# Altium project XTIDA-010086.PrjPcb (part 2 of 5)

## Sheet XTIDA-010086_Power Stage.SchDoc: Power Stage
size 558 x 431 mm; Date: Not shown in title block; ApprovedBy: Not shown in title block; CheckedBy: Not shown in title block; Author: Not shown in title block; CompanyName: Not shown in title block; DrawnBy: Jeff Xie; Engineer: Not shown in title block; Organization: Not shown in title block; Address1: Not shown in title block; Address2: Not shown in title block; Address3: Not shown in title block; Address4: Not shown in title block; DocumentNumber: 2; Revision: Use project parameter SCH_Rev; SheetNumber: 4; SheetTotal: 8; PageSetup: Record=PageOptions¦CenterHorizontal=True¦CenterVertical=True¦PrintScale=1.00¦XCorrection=1.00¦YCorrection=1.00¦PrintKind=0¦BorderSize=5000000¦LeftOffset=0¦BottomOffset=0¦Orientation=2¦PaperLength=1000¦PaperWidth=1000¦Scale=100¦PaperSource=15¦PrintQuality=600¦MediaType=1¦DitherType=10¦PaperKind=Letter¦PrintScaleMode=1
Used 8 times, as channels MAIN SHEET/Ch1, MAIN SHEET/Ch2, MAIN SHEET/Ch3, MAIN SHEET/Ch4, MAIN SHEET/Ch5, MAIN SHEET/Ch6, MAIN SHEET/Ch7, MAIN SHEET/Ch8. Parts and nets are listed once, with the designators drawn on the sheet.
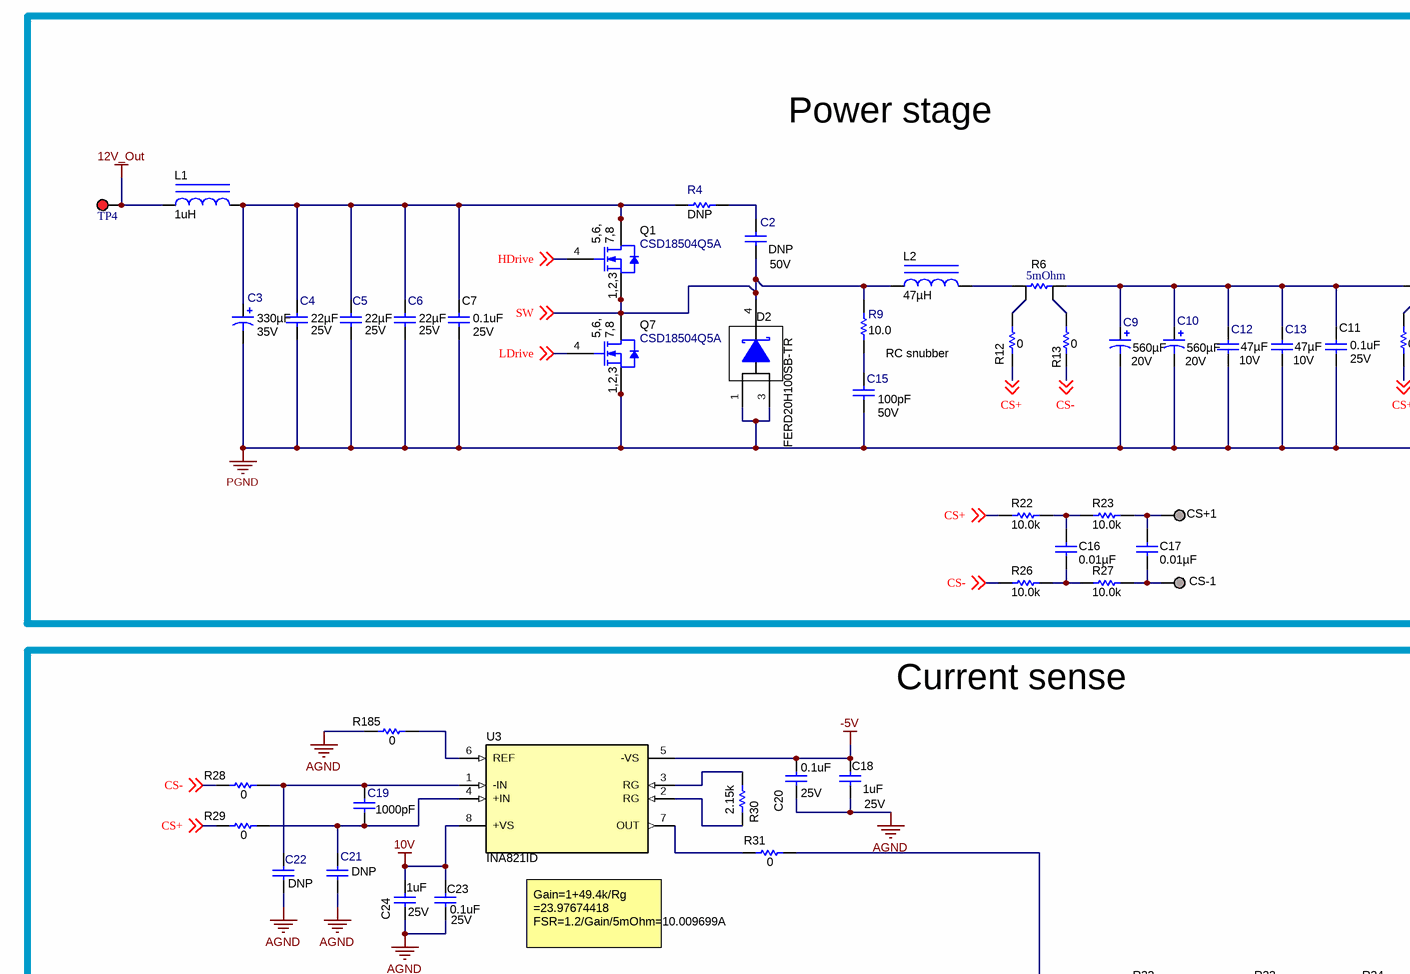
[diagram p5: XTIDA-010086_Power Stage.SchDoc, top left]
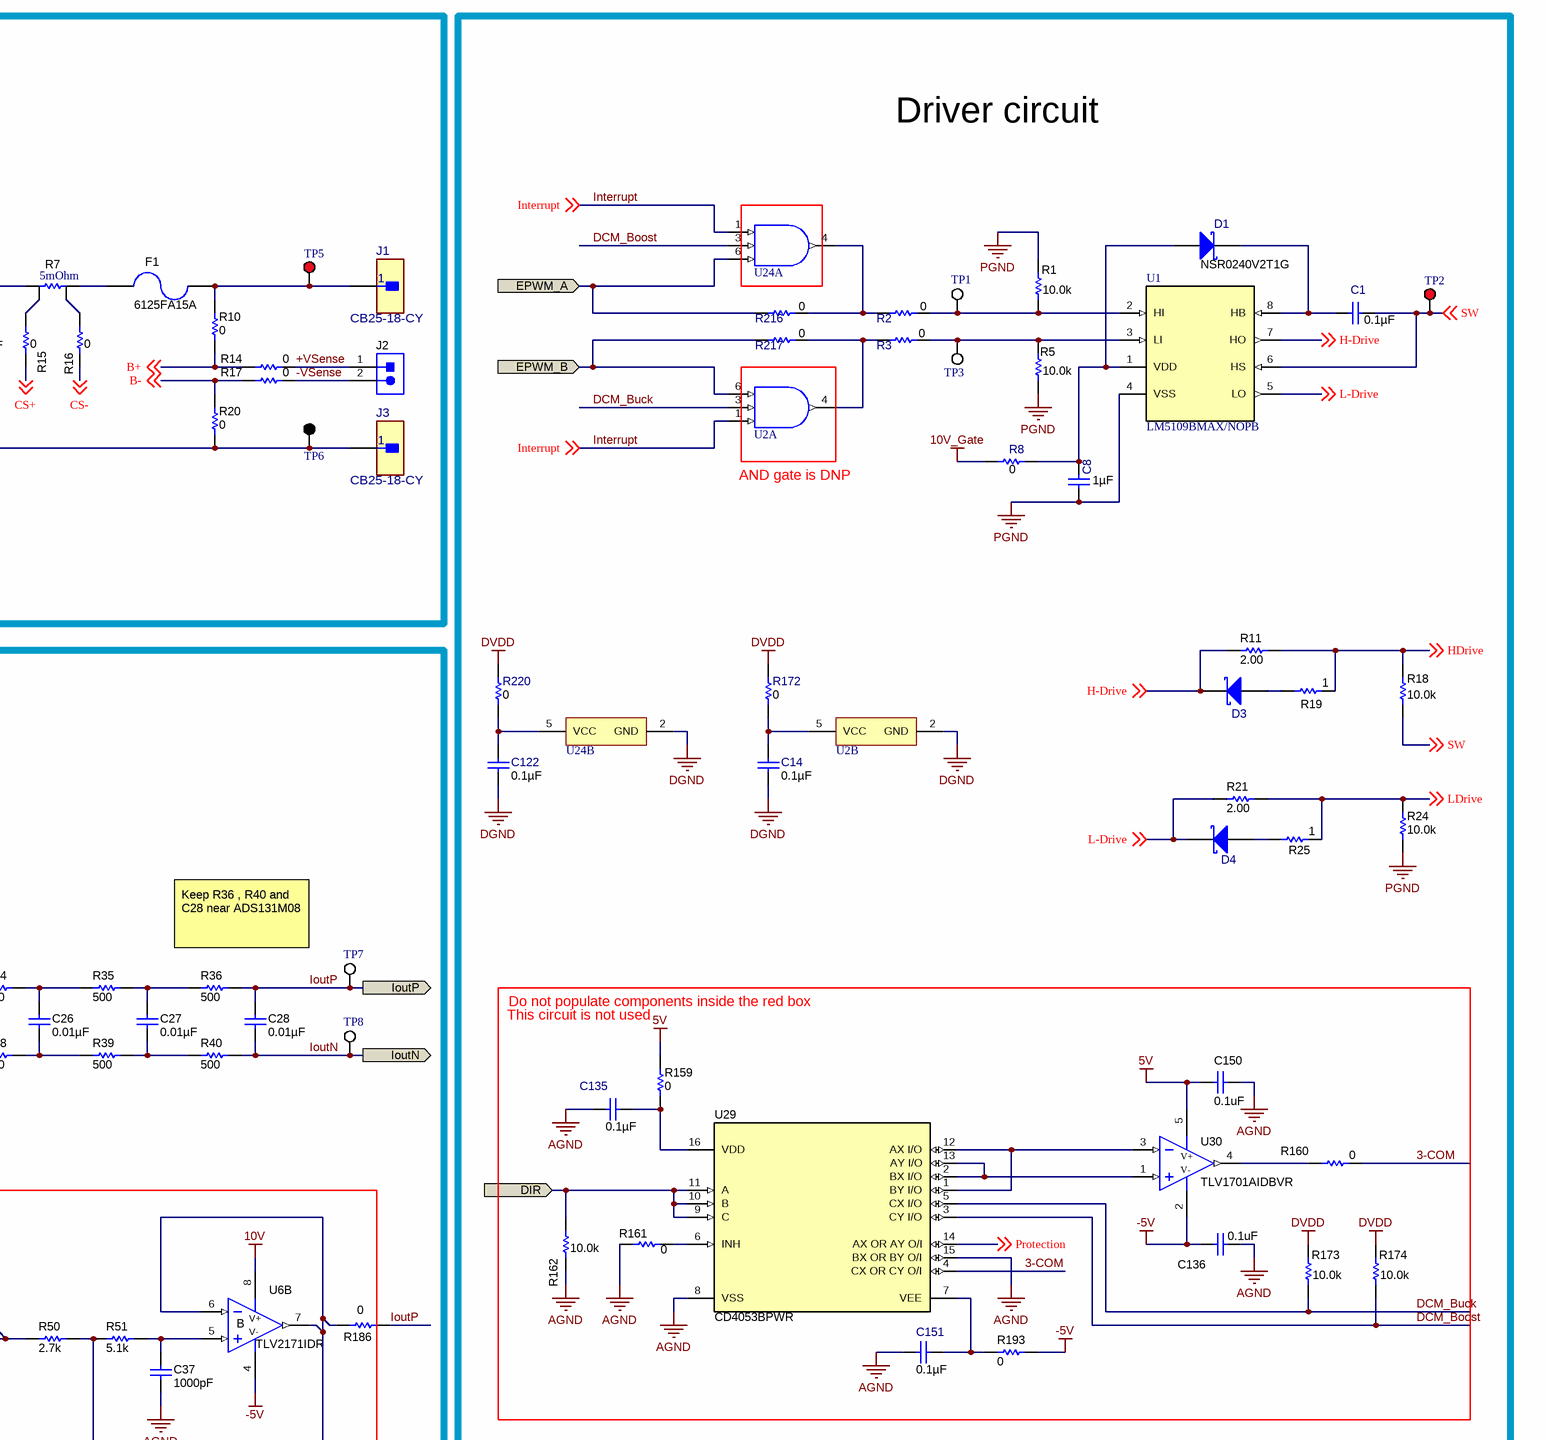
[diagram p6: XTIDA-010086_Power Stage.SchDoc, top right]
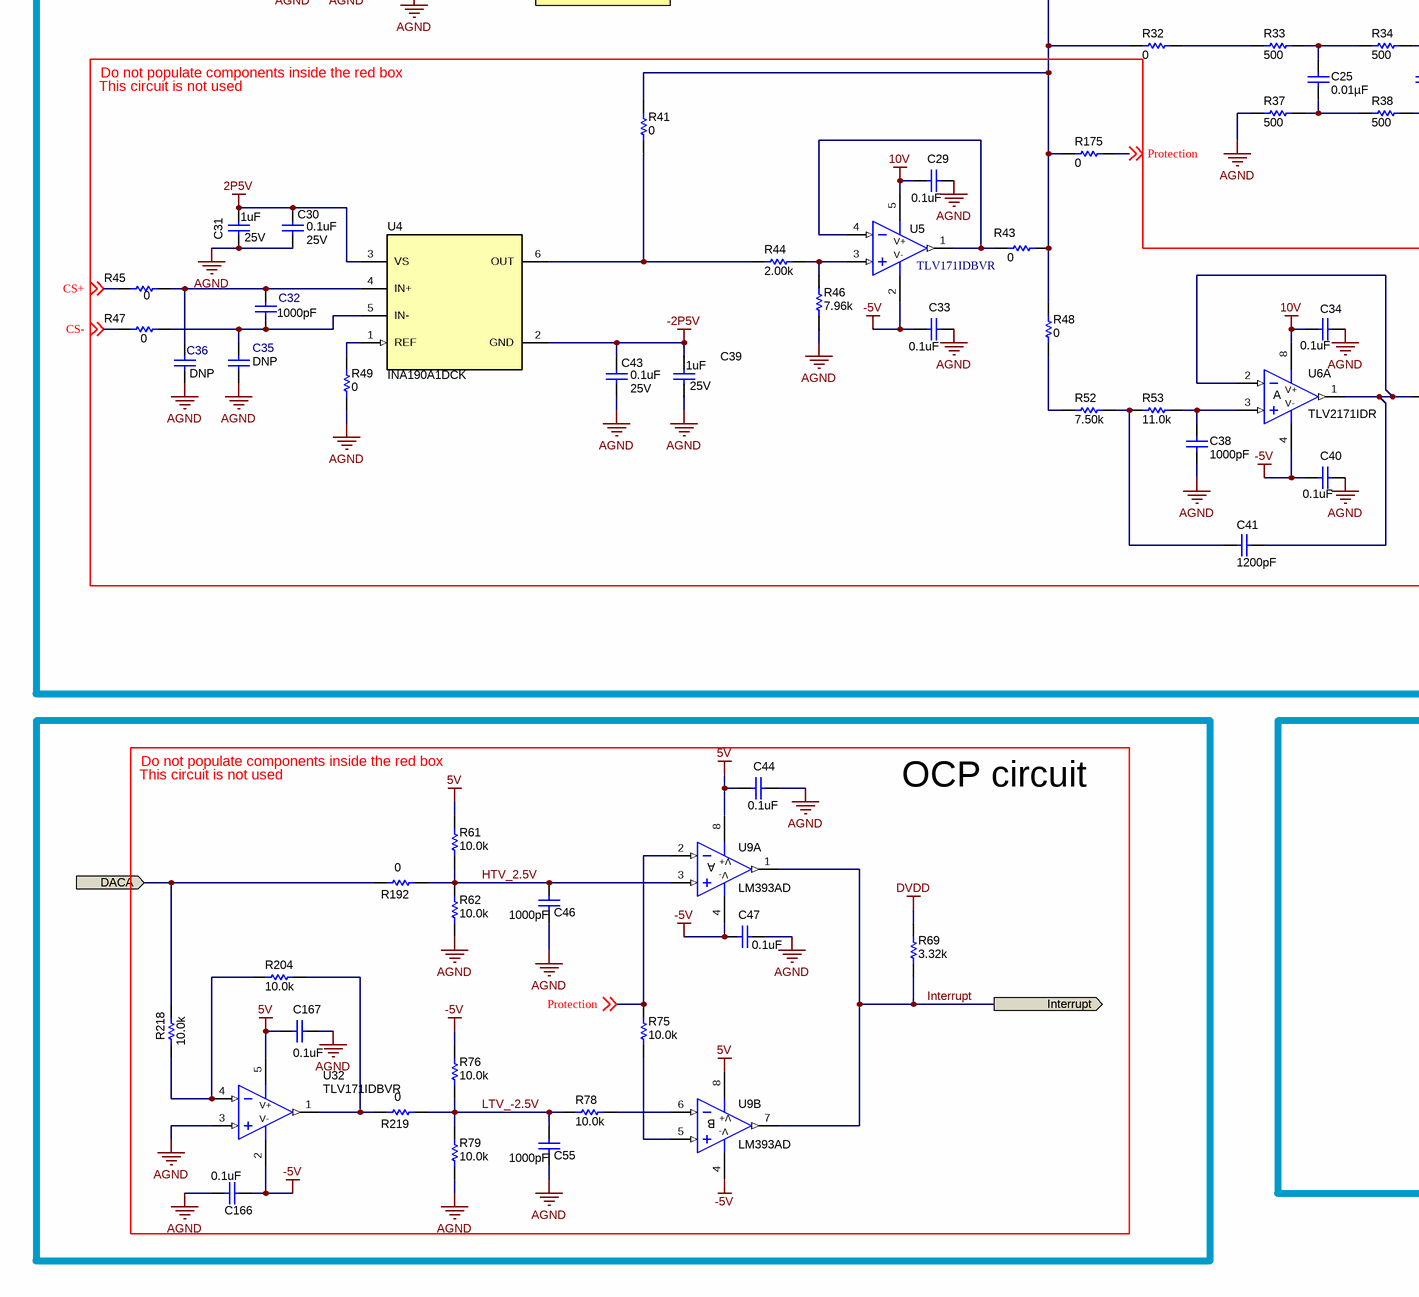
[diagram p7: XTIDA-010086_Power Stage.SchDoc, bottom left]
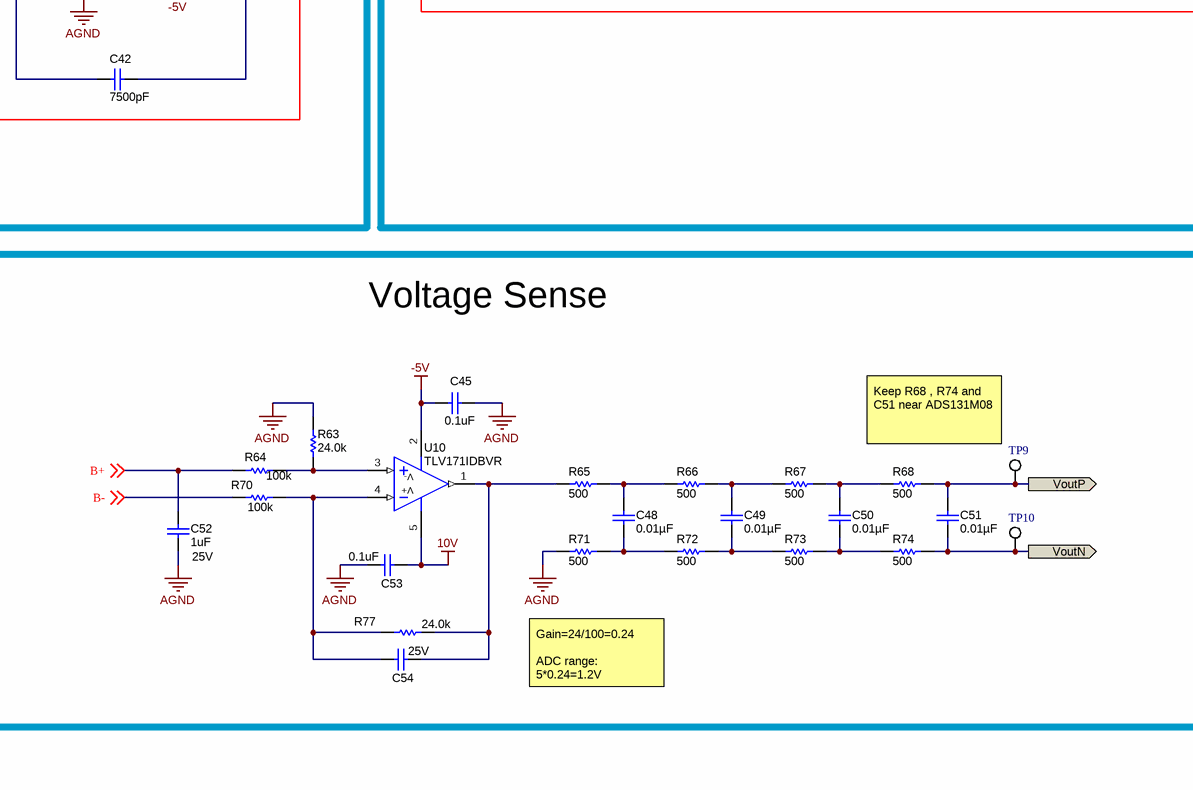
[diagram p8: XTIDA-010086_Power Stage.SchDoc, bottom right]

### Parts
C1  ValueDisplayed: 0.1µF  [0603L]  (hidden comment: C0603C104J3RACTU)
C2  ValueDisplayed: DNP  Value2: 50V  [0603L]  (hidden comment: GRM1885C1H101JA01D)
C3  ValueDisplayed: 330µF  Value2: 35V  [CAPSMT_62_F12]  (hidden comment: 35SVPK330M)
C4  ValueDisplayed: 22µF  Value2: 25V  [1210_270]  (hidden comment: GRM32ER71E226KE15L)
C5  ValueDisplayed: 22µF  Value2: 25V  [1210_270]  (hidden comment: GRM32ER71E226KE15L)
C6  ValueDisplayed: 22µF  Value2: 25V  [1210_270]  (hidden comment: GRM32ER71E226KE15L)
C7  ValueDisplayed: 0.1uF  Value2: 25V  [0603]  (hidden comment: Capacitor)
C8  ValueDisplayed: 1µF  [0603L]  (hidden comment: C0603C105K3RACTU)
C9  ValueDisplayed: 560µF  Value2: 20V  [SM_RADIAL_10AMM]  (hidden comment: 20SVF560M)
C10  ValueDisplayed: 560µF  Value2: 20V  [SM_RADIAL_10AMM]  (hidden comment: 20SVF560M)
C11  ValueDisplayed: 0.1uF  Value2: 25V  [0603]  (hidden comment: Capacitor)
C12  ValueDisplayed: 47µF  Value2: 10V  [1210_270]  (hidden comment: GRM32ER71A476ME15L)
C13  ValueDisplayed: 47µF  Value2: 10V  [1210_270]  (hidden comment: GRM32ER71A476ME15L)
C14  ValueDisplayed: 0.1µF  [0603L]  (hidden comment: C0603C104J3RACTU)
C15  ValueDisplayed: 100pF  Value2: 50V  [0603L]  (hidden comment: GRM1885C1H101JA01D)
C16  ValueDisplayed: 0.01µF  [0402]  (hidden comment: GCM155R71E103KA37D)
C17  ValueDisplayed: 0.01µF  [0402]  (hidden comment: GCM155R71E103KA37D)
C18  ValueDisplayed: 1uF  VDC_V: 25V  [0603]  (hidden comment: Capacitor)
C19  ValueDisplayed: 1000pF  [0603L]  (hidden comment: GRM1885C1H102JA01D)
C20  ValueDisplayed: 0.1uF  Value2: 25V  [0603]  (hidden comment: Capacitor)
C21  value DNP  [0603L]  (hidden comment: GRM1885C1H101JA01D)
C22  value DNP  [0603L]  (hidden comment: GRM1885C1H101JA01D)
C23  ValueDisplayed: 0.1uF  Value2: 25V  [0603]  (hidden comment: Capacitor)
C24  ValueDisplayed: 1uF  Value2: 25V  [0603]  (hidden comment: Capacitor)
C25  ValueDisplayed: 0.01µF  [0603]  (hidden comment: C0603C103J3GECAUTO)
C26  ValueDisplayed: 0.01µF  [0603]  (hidden comment: C0603C103J3GECAUTO)
C27  ValueDisplayed: 0.01µF  [0603]  (hidden comment: C0603C103J3GECAUTO)
C28  ValueDisplayed: 0.01µF  [0603]  (hidden comment: C0603C103J3GECAUTO)
C29  ValueDisplayed: 0.1uF  [0603]  (hidden comment: Capacitor)
C30  ValueDisplayed: 0.1uF  Value2: 25V  [0603]  (hidden comment: Capacitor)
C31  ValueDisplayed: 1uF  VDC_V: 25V  [0603]  (hidden comment: Capacitor)
C32  ValueDisplayed: 1000pF  [0603L]  (hidden comment: GRM1885C1H102JA01D)
C33  ValueDisplayed: 0.1uF  [0603]  (hidden comment: Capacitor)
C34  ValueDisplayed: 0.1uF  [0603]  (hidden comment: Capacitor)
C35  value DNP  [0603L]  (hidden comment: GRM1885C1H101JA01D)
C36  value DNP  [0603L]  (hidden comment: GRM1885C1H101JA01D)
C37  ValueDisplayed: 1000pF  [0402]  (hidden comment: 885012205044)
C38  ValueDisplayed: 1000pF  [0402]  (hidden comment: 885012205044)
C39  ValueDisplayed: 1uF  VDC_V: 25V  [0603]  (hidden comment: Capacitor)
C40  ValueDisplayed: 0.1uF  [0603]  (hidden comment: Capacitor)
C41  ValueDisplayed: 1200pF  [0402]  (hidden comment: GRM155R71H122KA01D)
C42  ValueDisplayed: 7500pF  [0805_HV]  (hidden comment: GRM2195C1H752JA01D)
C43  ValueDisplayed: 0.1uF  Value2: 25V  [0603]  (hidden comment: Capacitor)
C44  ValueDisplayed: 0.1uF  [0603]  (hidden comment: Capacitor)
C45  ValueDisplayed: 0.1uF  [0603]  (hidden comment: Capacitor)
C46  ValueDisplayed: 1000pF  [0603]  (hidden comment: 06031C102JAT2A)
C47  ValueDisplayed: 0.1uF  [0603]  (hidden comment: Capacitor)
C48  ValueDisplayed: 0.01µF  [0603]  (hidden comment: C0603C103J3GECAUTO)
C49  ValueDisplayed: 0.01µF  [0603]  (hidden comment: C0603C103J3GECAUTO)
C50  ValueDisplayed: 0.01µF  [0603]  (hidden comment: C0603C103J3GECAUTO)
C51  ValueDisplayed: 0.01µF  [0603]  (hidden comment: C0603C103J3GECAUTO)
C52  ValueDisplayed: 1uF  Value2: 25V  [0603]  (hidden comment: Capacitor)
C53  ValueDisplayed: 0.1uF  [0603]  (hidden comment: Capacitor)
C54  Value2: 25V  [0603]  (hidden comment: Capacitor)
C55  ValueDisplayed: 1000pF  [0603]  (hidden comment: 06031C102JAT2A)
C122  ValueDisplayed: 0.1µF  [0603L]  (hidden comment: C0603C104J3RACTU)
C135  ValueDisplayed: 0.1µF  [0603L]  (hidden comment: C0603C104J3RACTU)
C136  ValueDisplayed: 0.1uF  [0603]  (hidden comment: Capacitor)
C150  ValueDisplayed: 0.1uF  [0603]  (hidden comment: Capacitor)
C151  ValueDisplayed: 0.1µF  [0603L]  (hidden comment: C0603C104J3RACTU)
C166  ValueDisplayed: 0.1uF  [0603]  (hidden comment: Capacitor)
C167  ValueDisplayed: 0.1uF  [0603]  (hidden comment: Capacitor)
CS+1  TESTPOINT  [TP_25MIL-SMT]  (value not drawn)  (no BOM)
CS-1  TESTPOINT  [TP_25MIL-SMT]  (value not drawn)  (no BOM)
D1  NSR0240V2T1G  [SOD-523]
D2  FERD20H100SB-TR  [DPAK]
D3  NSR0240V2T1G  [SOD-523]  (value not drawn)
D4  NSR0240V2T1G  [SOD-523]  (value not drawn)
F1  6125FA15A  [6125FA]
J1  CB25-18-CY  [FP-CB25-18-CY_CONN_TERM_LUG_25MM4_7MM9-MFG]
J2  B2B-EH-A(LF)(SN)  [JST_B2B-EH-A]  (value not drawn)
J3  CB25-18-CY  [FP-CB25-18-CY_CONN_TERM_LUG_25MM4_7MM9-MFG]
L1  ValueDisplayed: 1uH  [WE-LHMI_4020]  (hidden comment: 74437324010)
L2  ValueDisplayed: 47µH  [WE-HCF Round_2920]  (hidden comment: 74437529203470)
Q1  CSD18504Q5A  [DQJ0008A]
Q7  CSD18504Q5A  [DQJ0008A]
R1  ValueDisplayed: 10.0k  [0603]  (hidden comment: RC0603FR-0710KL)
R2  ValueDisplayed: 0  [0603L]  (hidden comment: RC0603JR-070RL)
R3  ValueDisplayed: 0  [0603L]  (hidden comment: RC0603JR-070RL)
R4  ValueDisplayed: DNP  [1206L]  (hidden comment: RC1206FR-0710RL)
R5  ValueDisplayed: 10.0k  [0603]  (hidden comment: RC0603FR-0710KL)
R6  ValueDisplayed: 5mOhm  [CSM3637Z]  (hidden comment: Y14880R00500B9R)
R7  ValueDisplayed: 5mOhm  [CSM3637Z]  (hidden comment: Y14880R00500B9R)
R8  ValueDisplayed: 0  [0603L]  (hidden comment: RC0603JR-070RL)
R9  ValueDisplayed: 10.0  [1206L]  (hidden comment: RC1206FR-0710RL)
R10  ValueDisplayed: 0  [0402]  (hidden comment: CRCW04020000Z0ED)
R11  ValueDisplayed: 2.00  [0603]  (hidden comment: CRCW06032R00FKEA)
R12  ValueDisplayed: 0  [0402]  (hidden comment: CRCW04020000Z0ED)
R13  ValueDisplayed: 0  [0402]  (hidden comment: CRCW04020000Z0ED)
R14  ValueDisplayed: 0  [0402]  (hidden comment: CRCW04020000Z0ED)
R15  ValueDisplayed: 0  [0402]  (hidden comment: CRCW04020000Z0ED)
R16  ValueDisplayed: 0  [0402]  (hidden comment: CRCW04020000Z0ED)
R17  ValueDisplayed: 0  [0402]  (hidden comment: CRCW04020000Z0ED)
R18  ValueDisplayed: 10.0k  [0603]  (hidden comment: RC0603FR-0710KL)
R19  ValueDisplayed: 1  [0603]  (hidden comment: RC0603FR-071RL)
R20  ValueDisplayed: 0  [0402]  (hidden comment: CRCW04020000Z0ED)
R21  ValueDisplayed: 2.00  [0603]  (hidden comment: CRCW06032R00FKEA)
R22  ValueDisplayed: 10.0k  [0402]  (hidden comment: CRCW040210K0FKED)
R23  ValueDisplayed: 10.0k  [0402]  (hidden comment: CRCW040210K0FKED)
R24  ValueDisplayed: 10.0k  [0603]  (hidden comment: RC0603FR-0710KL)
R25  ValueDisplayed: 1  [0603]  (hidden comment: RC0603FR-071RL)
R26  ValueDisplayed: 10.0k  [0402]  (hidden comment: CRCW040210K0FKED)
R27  ValueDisplayed: 10.0k  [0402]  (hidden comment: CRCW040210K0FKED)
R28  ValueDisplayed: 0  [0402]  (hidden comment: CRCW04020000Z0ED)
R29  ValueDisplayed: 0  [0402]  (hidden comment: CRCW04020000Z0ED)
R30  ValueDisplayed: 2.15k  [0603]  (hidden comment: RT0603BRD072K15L)
R31  ValueDisplayed: 0  [0402]  (hidden comment: CRCW04020000Z0ED)
R32  ValueDisplayed: 0  [0402]  (hidden comment: CRCW04020000Z0ED)
R33  ValueDisplayed: 500  [0402]  (hidden comment: PNM0402E5000BST1)
R34  ValueDisplayed: 500  [0402]  (hidden comment: PNM0402E5000BST1)
R35  ValueDisplayed: 500  [0402]  (hidden comment: PNM0402E5000BST1)
R36  ValueDisplayed: 500  [0402]  (hidden comment: PNM0402E5000BST1)
R37  ValueDisplayed: 500  [0402]  (hidden comment: PNM0402E5000BST1)
R38  ValueDisplayed: 500  [0402]  (hidden comment: PNM0402E5000BST1)
R39  ValueDisplayed: 500  [0402]  (hidden comment: PNM0402E5000BST1)
R40  ValueDisplayed: 500  [0402]  (hidden comment: PNM0402E5000BST1)
R41  ValueDisplayed: 0  [0402]  (hidden comment: CRCW04020000Z0ED)
R43  ValueDisplayed: 0  [0402]  (hidden comment: CRCW04020000Z0ED)
R44  ValueDisplayed: 2.00k  [0603]  (hidden comment: RT0603BRD072KL)
R45  ValueDisplayed: 0  [0402]  (hidden comment: CRCW04020000Z0ED)
R46  ValueDisplayed: 7.96k  [0603]  (hidden comment: RT0603BRD077K96L)
R47  ValueDisplayed: 0  [0402]  (hidden comment: CRCW04020000Z0ED)
R48  ValueDisplayed: 0  [0402]  (hidden comment: CRCW04020000Z0ED)
R49  ValueDisplayed: 0  [0402]  (hidden comment: CRCW04020000Z0ED)
R50  ValueDisplayed: 2.7k  [0402]  (hidden comment: CRCW04022K70JNED)
R51  ValueDisplayed: 5.1k  [0402]  (hidden comment: CRCW04025K10JNED)
R52  ValueDisplayed: 7.50k  [0402]  (hidden comment: CRCW04027K50FKED)
R53  ValueDisplayed: 11.0k  [0402]  (hidden comment: CRCW040211K0FKED)
R61  ValueDisplayed: 10.0k  [0402]  (hidden comment: CRCW040210K0FKED)
R62  ValueDisplayed: 10.0k  [0402]  (hidden comment: CRCW040210K0FKED)
R63  ValueDisplayed: 24.0k  [0603]  (hidden comment: RT0603BRD0724KL)
R64  ValueDisplayed: 100k  [0603]  (hidden comment: RT0603BRD07100KL)
R65  ValueDisplayed: 500  [0402]  (hidden comment: PNM0402E5000BST1)
R66  ValueDisplayed: 500  [0402]  (hidden comment: PNM0402E5000BST1)
R67  ValueDisplayed: 500  [0402]  (hidden comment: PNM0402E5000BST1)
R68  ValueDisplayed: 500  [0402]  (hidden comment: PNM0402E5000BST1)
R69  ValueDisplayed: 3.32k  [0603]  (hidden comment: CRCW06033K32FKEA)
R70  ValueDisplayed: 100k  [0603]  (hidden comment: RT0603BRD07100KL)
R71  ValueDisplayed: 500  [0402]  (hidden comment: PNM0402E5000BST1)
R72  ValueDisplayed: 500  [0402]  (hidden comment: PNM0402E5000BST1)
R73  ValueDisplayed: 500  [0402]  (hidden comment: PNM0402E5000BST1)
R74  ValueDisplayed: 500  [0402]  (hidden comment: PNM0402E5000BST1)
R75  ValueDisplayed: 10.0k  [0603]  (hidden comment: CRCW060310K0FKEA)
R76  ValueDisplayed: 10.0k  [0402]  (hidden comment: CRCW040210K0FKED)
R77  ValueDisplayed: 24.0k  [0603]  (hidden comment: RT0603BRD0724KL)
R78  ValueDisplayed: 10.0k  [0603]  (hidden comment: CRCW060310K0FKEA)
R79  ValueDisplayed: 10.0k  [0402]  (hidden comment: CRCW040210K0FKED)
R159  ValueDisplayed: 0  [0402]  (hidden comment: CRCW04020000Z0ED)
R160  ValueDisplayed: 0  [0402]  (hidden comment: CRCW04020000Z0ED)
R161  ValueDisplayed: 0  [0402]  (hidden comment: CRCW04020000Z0ED)
R162  ValueDisplayed: 10.0k  [0402]  (hidden comment: CRCW040210K0FKED)
R172  ValueDisplayed: 0  [0603L]  (hidden comment: RC0603JR-070RL)
R173  ValueDisplayed: 10.0k  [0603]  (hidden comment: RC0603FR-0710KL)
R174  ValueDisplayed: 10.0k  [0603]  (hidden comment: RC0603FR-0710KL)
R175  ValueDisplayed: 0  [0402]  (hidden comment: CRCW04020000Z0ED)
R185  ValueDisplayed: 0  [0402]  (hidden comment: CRCW04020000Z0ED)
R186  ValueDisplayed: 0  [0402]  (hidden comment: CRCW04020000Z0ED)
R192  ValueDisplayed: 0  [0402]  (hidden comment: CRCW04020000Z0ED)
R193  ValueDisplayed: 0  [0402]  (hidden comment: CRCW04020000Z0ED)
R204  ValueDisplayed: 10.0k  [0402]  (hidden comment: CRCW040210K0FKED)
R216  ValueDisplayed: 0  [0603L]  (hidden comment: RC0603JR-070RL)
R217  ValueDisplayed: 0  [0603L]  (hidden comment: RC0603JR-070RL)
R218  ValueDisplayed: 10.0k  [0402]  (hidden comment: CRCW040210K0FKED)
R219  ValueDisplayed: 0  [0402]  (hidden comment: CRCW04020000Z0ED)
R220  ValueDisplayed: 0  [0603L]  (hidden comment: RC0603JR-070RL)
TP1  5002  [Keystone5002]  (value not drawn)
TP2  5000  [Keystone5000]  (value not drawn)
TP3  5002  [Keystone5002]  (value not drawn)
TP4  5000  [Keystone5000]  (value not drawn)
TP5  5000  [Keystone5000]  (value not drawn)
TP6  5001  [Keystone5001]  (value not drawn)
TP7  5002  [Keystone5002]  (value not drawn)
TP8  5002  [Keystone5002]  (value not drawn)
TP9  5002  [Keystone5002]  (value not drawn)
TP10  5002  [Keystone5002]  (value not drawn)
U1  LM5109BMAX/NOPB  [D0008A_N]
U2  SN74LVC1G11DCKR  [DCK0006A_N]  (value not drawn)  (parts A,B of 2)
U3  INA821ID  [D0008A_N]
U4  INA190A1DCK  [DCK0006A_N]
U5  TLV171IDBVR  [DBV0005A_N]
U6  TLV2171IDR  [D0008A_N]  (parts A,B of 2)
U9  LM393AD  [D0008A_N]  (parts A,B of 2)
U10  TLV171IDBVR  [DBV0005A_N]
U24  SN74LVC1G11DCKR  [DCK0006A_N]  (value not drawn)  (parts A,B of 2)
U29  CD4053BPWR  [PW0016A_L]
U30  TLV1701AIDBVR  [DBV0005A_N]
U32  TLV171IDBVR  [DBV0005A_N]

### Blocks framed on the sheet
Power stage: C2-C7 C9-C13 C15-C17 CS+1 CS-1 D2 F1 J1-J3 L1 L2 Q1 Q7 R4 R6 R7 R9 R10 R12-R17 R20 R22 R23 R26 R27 TP4-TP6
Driver circuit: C1 C8 C14 C122 C135 C136 C150 C151 D1 D3 D4 R1-R3 R5 R8 R11 R18 R19 R21 R24 R25 R159-R162 R172-R174 R193 R216 R217 R220 TP1-TP3 U1 U2 U24 U29 U30
Current sense: C18-C43 R28-R41 R43-R53 R175 R185 R186 TP7 TP8 U3-U6
OCP circuit: C44 C46 C47 C55 C166 C167 R61 R62 R69 R75 R76 R78 R79 R192 R204 R218 R219 U9 U32
Voltage Sense: C45 C48-C54 R63-R68 R70-R74 R77 TP9 TP10 U10

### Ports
DACA (in), DIR (in), EPWM_A (in), EPWM_B (in), Interrupt (out), IoutN (out), IoutP (out), VoutN (out), VoutP (out)

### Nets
2P5V: C30.1 C31.1 U4.3(VS)
5V: C44.1 C150.1 C167.1 R61.2 R159.2 U9.8(V+) U30.5(V+) U32.5(V+)
10V: C23.1 C24.1 C29.1 C34.1 C53.1 U3.8(+VS) U5.5(V+) U6.8(V+) U10.5(V+)
10V_Gate: R8.2
12V_Out: L1.1 TP4.1
-2P5V: C39.1 C43.1 U4.2(GND)
-5V: C18.1 C20.1 C33.1 C40.1 C45.1 C47.1 C136.1 C166.1 R76.2 R193.1 U3.5(-VS) U5.2(V-) U6.4(V-) U9.4(V-) U10.2(V-) U30.2(V-) U32.2(V-)
AGND: C18.2 C20.2 C21.1 C22.2 C23.2 C24.2 C29.2 C30.2 C31.2 C33.2 C34.2 C35.1 C36.2 C37.2 C38.2 C39.2 C40.2 C43.2 C44.2 C45.2 C46.1 C47.2 C52.2 C53.2 C55.1 C135.2 C136.2 C150.2 C151.1 C166.2 C167.2 R37.1 R46.1 R49.2 R62.1 R63.2 R71.1 R79.1 R161.1 R162.2 R185.1 U29.8(VSS) U29.15(BX_OR_BY_O/I) U32.3(IN+)
DGND: C14.1 C122.1 U2.2(GND) U24.2(GND)
DVDD: R69.2 R172.1 R173.2 R174.2 R220.1
PGND: C3.2(-) C4.2 C5.2 C6.2 C7.2 C8.1 C9.2(-) C10.2(-) C11.2 C12.2 C13.2 C15.1 D2.1(A) D2.3(A) J3.1 Q7.1(S) Q7.2(S) Q7.3(S) R1.2 R5.1 R20.1 R24.1 TP6.1 U1.4(VSS)
3-COM: R160.2 U29.4(CX_OR_CY_O/I)
+VSense: J2.1 R14.2
-VSense: J2.2 R17.2
B+: C52.1 R10.1 R14.1 R64.1 ; off-sheet B+
B-: R17.1 R20.2 R70.1 ; off-sheet B-
CS+: R12.1 R15.1 R22.1 R29.1 R45.1 ; off-sheet CS+
CS-: R13.1 R16.1 R26.1 R28.1 R47.1 ; off-sheet CS-
DACA: R192.1 R218.2 ; port DACA
DCM_Boost: R174.1 U24.3(B) U29.3(CY_I/O)
DCM_Buck: R173.1 U2.3(B) U29.5(CX_I/O)
DIR: R162.1 U29.9(C) U29.10(B) U29.11(A) ; port DIR
EPWM_A: R216.2 U24.6(C) ; port EPWM_A
EPWM_B: R217.2 U2.6(C) ; port EPWM_B
H-Drive: D3.1(K) R11.2 U1.7(HO) ; off-sheet H-Drive
HDrive: Q1.4(G) R11.1 R18.2 R19.2 ; off-sheet HDrive
HTV_2.5V: C46.2 R61.1 R62.2 R192.2 U9.3(IN+)
Interrupt: R69.1 U2.1(A) U9.1(OUT) U9.7(OUT) U24.1(A) ; off-sheet Interrupt, port Interrupt
IoutN: C28.2 R40.2 TP8.1 ; port IoutN
IoutP: C28.1 R36.2 R186.2 TP7.1 ; port IoutP
L-Drive: D4.1(K) R21.2 U1.5(LO) ; off-sheet L-Drive
LDrive: Q7.4(G) R21.1 R24.2 R25.2 ; off-sheet LDrive
LTV_-2.5V: C55.2 R76.1 R78.2 R79.2 R219.2
Protection: R75.1 R175.1 U9.2(IN-) U29.14(AX_OR_AY_O/I) ; off-sheet Protection
SW: C1.2 C2.1 D2.4(K) L2.1 Q1.1(S) Q1.2(S) Q1.3(S) Q7.5(D) Q7.6(D) Q7.7(D) Q7.8(D) Q7.9(D) R9.1 R18.1 TP2.1 U1.6(HS) ; off-sheet SW
VoutN: C51.2 R74.2 TP10.1 ; port VoutN
VoutP: C51.1 R68.2 TP9.1 ; port VoutP
NetC1_1: C1.1 D1.1(K) U1.8(HB)
NetC2_2: C2.2 R4.2
NetC3_1: C3.1(+) C4.1 C5.1 C6.1 C7.1 L1.2 Q1.5(D) Q1.6(D) Q1.7(D) Q1.8(D) Q1.9(D) R4.1
NetC8_2: C8.2 D1.2(A) R8.1 U1.1(VDD)
NetC9_1: C9.1(+) C10.1(+) C11.1 C12.1 C13.1 R6.1 R7.2
NetC14_2: C14.2 R172.2 U2.5(VCC)
NetC15_2: C15.2 R9.2
NetC16_1: C16.1 R22.2 R23.1
NetC16_2: C16.2 R26.2 R27.1
NetC17_1: C17.1 CS+1.1 R23.2
NetC17_2: C17.2 CS-1.1 R27.2
NetC19_1: C19.1 C22.1 R28.2 U3.1(-IN)
NetC19_2: C19.2 C21.2 R29.2 U3.4(+IN)
NetC25_1: C25.1 R33.2 R34.1
NetC25_2: C25.2 R37.2 R38.1
NetC26_1: C26.1 R34.2 R35.1
NetC26_2: C26.2 R38.2 R39.1
NetC27_1: C27.1 R35.2 R36.1
NetC27_2: C27.2 R39.2 R40.1
NetC32_1: C32.1 C36.1 R45.2 U4.4(IN+)
NetC32_2: C32.2 C35.2 R47.2 U4.5(IN-)
NetC37_1: C37.1 R51.2 U6.5(IN+)
NetC38_1: C38.1 R53.2 U6.3(IN+)
NetC41_1: C41.1 R50.1 U6.1(OUT) U6.2(IN-)
NetC41_2: C41.2 R52.2 R53.1
NetC42_1: C42.1 R186.1 U6.6(IN-) U6.7(OUT)
NetC42_2: C42.2 R50.2 R51.1
NetC48_1: C48.1 R65.2 R66.1
NetC48_2: C48.2 R71.2 R72.1
NetC49_1: C49.1 R66.2 R67.1
NetC49_2: C49.2 R72.2 R73.1
NetC50_1: C50.1 R67.2 R68.1
NetC50_2: C50.2 R73.2 R74.1
NetC54_1: C54.1 R70.2 R77.1 U10.4(IN-)
NetC54_2: C54.2 R65.1 R77.2 U10.1(OUT)
NetC122_2: C122.2 R220.2 U24.5(VCC)
NetC135_1: C135.1 R159.1 U29.16(VDD)
NetC151_2: C151.2 R193.2 U29.7(VEE)
NetD3_2: D3.2(A) R19.1
NetD4_2: D4.2(A) R25.1
NetF1_1: F1.1 J1.1 R10.2 TP5.1
NetF1_2: F1.2 R7.1
NetL2_2: L2.2 R6.2
NetR1_1: R1.1 R2.1 TP1.1 U1.2(HI)
NetR2_2: R2.2 R216.1 U24.4(Y)
NetR3_1: R3.1 R5.2 TP3.1 U1.3(LI)
NetR3_2: R3.2 R217.1 U2.4(Y)
NetR6_3: R6.3 R13.2
NetR6_4: R6.4 R12.2
NetR7_3: R7.3 R16.2
NetR7_4: R7.4 R15.2
NetR30_1: R30.1 U3.3(RG)
NetR30_2: R30.2 U3.2(RG)
NetR31_1: R31.1 U3.7(OUT)
NetR31_2: R31.2 R32.1 R41.1 R43.1 R48.1 R175.2
NetR32_2: R32.2 R33.1
NetR41_2: R41.2 R44.1 U4.6(OUT)
NetR43_2: R43.2 U5.1(OUT) U5.4(IN-)
NetR44_2: R44.2 R46.2 U5.3(IN+)
NetR48_2: R48.2 R52.1
NetR49_1: R49.1 U4.1(REF)
NetR63_1: R63.1 R64.2 U10.3(IN+)
NetR75_2: R75.2 U9.5(IN+)
NetR78_1: R78.1 U9.6(IN-)
NetR160_1: R160.1 U30.4(OUT)
NetR161_2: R161.2 U29.6(INH)
NetR185_2: R185.2 U3.6(REF)
NetR204_1: R204.1 R219.1 U32.1(OUT)
NetR204_2: R204.2 R218.1 U32.4(IN-)
NetU29_1: U29.1(BY_I/O) U29.12(AX_I/O) U30.3(IN-)
NetU29_2: U29.2(BX_I/O) U29.13(AY_I/O) U30.1(IN+)

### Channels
MAIN SHEET/Ch1: designators end in _Ch1; ports DACA=DACA DIR=DIR EPWM_A=EPWM_A EPWM_B=EPWM_B Interrupt=Interrupt IoutN=IoutN IoutP=IoutP VoutN=VoutN VoutP=VoutP
MAIN SHEET/Ch2: designators end in _Ch2; ports DACA=DACA DIR=DIR EPWM_A=EPWM_A EPWM_B=EPWM_B Interrupt=Interrupt IoutN=IoutN IoutP=IoutP VoutN=VoutN VoutP=VoutP
MAIN SHEET/Ch3: designators end in _Ch3; ports DACA=DACA DIR=DIR EPWM_A=EPWM_A EPWM_B=EPWM_B Interrupt=Interrupt IoutN=IoutN IoutP=IoutP VoutN=VoutN VoutP=VoutP
MAIN SHEET/Ch4: designators end in _Ch4; ports DACA=DACA DIR=DIR EPWM_A=EPWM_A EPWM_B=EPWM_B Interrupt=Interrupt IoutN=IoutN IoutP=IoutP VoutN=VoutN VoutP=VoutP
MAIN SHEET/Ch5: designators end in _Ch5; ports DACA=DACA DIR=DIR EPWM_A=EPWM_A EPWM_B=EPWM_B Interrupt=Interrupt IoutN=IoutN IoutP=IoutP VoutN=VoutN VoutP=VoutP
MAIN SHEET/Ch6: designators end in _Ch6; ports DACA=DACA DIR=DIR EPWM_A=EPWM_A EPWM_B=EPWM_B Interrupt=Interrupt IoutN=IoutN IoutP=IoutP VoutN=VoutN VoutP=VoutP
MAIN SHEET/Ch7: designators end in _Ch7; ports DACA=DACA DIR=DIR EPWM_A=EPWM_A EPWM_B=EPWM_B Interrupt=Interrupt IoutN=IoutN IoutP=IoutP VoutN=VoutN VoutP=VoutP
MAIN SHEET/Ch8: designators end in _Ch8; ports DACA=DACA DIR=DIR EPWM_A=EPWM_A EPWM_B=EPWM_B Interrupt=Interrupt IoutN=IoutN IoutP=IoutP VoutN=VoutN VoutP=VoutP

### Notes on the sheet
- RC snubber
- (near U2) AND gate is DNP
- Gain=1+49.4k/Rg
  =23.97674418
  FSR=1.2/Gain/5mOhm=10.009699A
- Keep R36 , R40 and C28 near ADS131M08
- Do not populate components inside the red box
- (near R159) This circuit is not used
- This circuit is not used
- Keep R68 , R74 and C51 near ADS131M08
- Gain=24/100=0.24
  ADC range: 5*0.24=1.2V

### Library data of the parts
C1 C14 C122 C135 C151 = C0603C104J3RACTU: CAP, CERM, 0.1 µF, 25 V, +/- 5%, X7R, 0603; Manufacturer: Kemet; Polarized: N; CompType: Capacitor; Value: 0.1uF; U/M: EA; Cap_F: 0.0000001; Tolerance_%: 5; Value1: Unknown; VDC_V: 25; Value2: 25V; TaMin_C: -55; TaMax_C: 125; Cap_Case: 0603; SizeArea_mm2: 1.28; SizeAreaWB_mm2: 4.68; SizeX_mm: 1.6; SizeY_mm: 0.8; SizeZ_mm: 1; AEC Category: Q200
C2 C15 = GRM1885C1H101JA01D: CAP, CERM, 100 pF, 50 V, +/- 5%, C0G/NP0, 0603; Manufacturer: MuRata; Polarized: N; CompType: Capacitor; Value: 100pF; U/M: EA; Cap_F: 0.0000000001; Tolerance_%: 5; Value1: Unknown; VDC_V: 50; TaMin_C: -55; TaMax_C: 125; Cap_Case: 0603; SizeArea_mm2: 1.28; SizeAreaWB_mm2: 4.68; SizeX_mm: 1.6; SizeY_mm: 0.8; SizeZ_mm: 1; AEC Category: Q200
C3 = 25SVPF330M: 330µF 35V Aluminum Polymer Capacitor Radial, Can - SMD 18mOhm 1000 Hrs @ 125°C; Manufacturer: Panasonic; Polarized: Y; Value: 330uF; U/M: EA; Cap_F: 0.00033; Tolerance_%: 20; Value1: 0.014 ohm; VDC_V: 35; ESR_ohm: 0.014; IRMS_A: 5; TaMin_C: -55; TaMax_C: 105; Cap_Case: F12; SizeAreaWB_mm2: 151.29; SizeArea_mm2: 106.09; SizeX_mm: 10.3; SizeZ_mm: 12.6; AEC Category: Q200; AEC Qualified: N
C4-C6 = GRM32ER71E226KE15L: CAP, CERM, 22 µF, 25 V, +/- 10%, X7R, 1210; Manufacturer: MuRata; Polarized: N; CompType: Capacitor; Value: 22uF; U/M: EA; Cap_F: 0.000022; Tolerance_%: 10; Value1: Unknown; VDC_V: 25; TaMin_C: -55; TaMax_C: 125; Cap_Case: 1210; SizeArea_mm2: 8; SizeAreaWB_mm2: 14.7; SizeX_mm: 3.2; SizeY_mm: 2.5; SizeZ_mm: 2.7; AEC Category: Q200
C7 C11 C20 C23 C30 C43 C54 = CMP-0006752-5: CAP, CERM, 0.1 uF, 25 V, +/- 5%, X7R, 0603; PartNumber: 06033C104JAT2A; Manufacturer: AVX; Polarized: N; Value: 0.1uF; U/M: EA; Cap_F: 100nF; ESR_ohm: 0.05; Value1: 0.05 ohm; TaMin_C: -55°C; TaMax_C: 125°C; AEC Category: Q200; SizeArea_mm2: 1.28; SizeAreaWB_mm2: 4.68; SizeX_mm: 1.6; SizeY_mm: 0.8; SizeZ_mm: 1
C8 = C0603C105K3RACTU: CAP, CERM, 1 µF, 25 V, +/- 10%, X7R, 0603; Manufacturer: Kemet; Polarized: N; CompType: Capacitor; Value: 1uF; U/M: EA; Cap_F: 0.000001; Tolerance_%: 10; Value1: Unknown; VDC_V: 25; Value2: 25V; TaMin_C: -55; TaMax_C: 125; Cap_Case: 0603; SizeArea_mm2: 1.28; SizeAreaWB_mm2: 4.68; SizeX_mm: 1.6; SizeY_mm: 0.8; SizeZ_mm: 1; AEC Category: Q200
C9 C10 = 10SVP560M: 560µF 20V Aluminum Polymer Capacitor Radial, Can - SMD 12mOhm 1000 Hrs @ 125°C; Manufacturer: Panasonic; Polarized: Y; Value: 560uF; U/M: EA; Cap_F: 0.00056; Tolerance_%: 20; Value1: 0.013 ohm; ESR_ohm: 0.013; IRMS_A: 5.23; TaMin_C: -55; TaMax_C: 105; Cap_Case: 10.3x10.3x12.6; SizeAreaWB_mm2: 159.9; SizeArea_mm2: 113.3; SizeX_mm: 11; SizeY_mm: 10.3; SizeZ_mm: 7.7; AEC Category: Q200
C12 C13 = GRM32ER71A476ME15L: CAP, CERM, 47 µF, 10 V, +/- 20%, X7R, 1210; Manufacturer: MuRata; Polarized: N; CompType: Capacitor; Value: 47uF; U/M: EA; Cap_F: 0.000047; Tolerance_%: 20; Value1: Unknown; VDC_V: 10; TaMin_C: -55; TaMax_C: 125; Cap_Case: 1210; SizeArea_mm2: 8; SizeAreaWB_mm2: 14.7; SizeX_mm: 3.2; SizeY_mm: 2.5; SizeZ_mm: 2.7; AEC Category: Q200
C16 C17 = GCM155R71E103KA37D: CAP, CERM, 0.01 µF, 25 V,+/- 10%, X7R, 0402; Manufacturer: MuRata; Polarized: N; CompType: Capacitor; Value: 0.01uF; U/M: EA; Cap_F: 0.00000001; Tolerance_%: 10; VDC_V: 25; Value2: 25V; TaMin_C: -55; TaMax_C: 125; SizeArea_mm2: 0.5; SizeAreaWB_mm2: 3; SizeX_mm: 1; SizeZ_mm: 0.6; AEC Category: Q200; Green_Lifecycle: Active; Green_REACh: Passed
C18 C24 C31 C39 C52 = CMP-0007405-4: CAP, CERM, 1 uF, 25 V, +/- 10%, X7R, 0603; PartNumber: GRM188R71E105KA12D; Manufacturer: MuRata; Polarized: N; Value: 1uF; U/M: EA; Cap_F: 1µF; Value1: Unknown; TaMin_C: -55°C; TaMax_C: 125°C; AEC Category: Q200; SizeArea_mm2: 1.28; SizeAreaWB_mm2: 4.68; SizeX_mm: 1.6; SizeY_mm: 0.8; SizeZ_mm: 1
C19 C32 = GRM1885C1H102JA01D: CAP, CERM, 1000 pF, 50 V, +/- 5%, C0G/NP0, 0603; Manufacturer: MuRata; Polarized: N; CompType: Capacitor; Value: 1000pF; U/M: EA; Cap_F: 0.000000001; Tolerance_%: 5; Value1: Unknown; VDC_V: 50; Value2: 50V; TaMin_C: -55; TaMax_C: 125; Cap_Case: 0603; SizeArea_mm2: 1.28; SizeAreaWB_mm2: 4.68; SizeX_mm: 1.6; SizeY_mm: 0.8; SizeZ_mm: 1; AEC Category: Q200
C21 C22 C35 C36 = GRM1885C1H101JA01D: CAP, CERM, 100 pF, 50 V, +/- 5%, C0G/NP0, 0603; Manufacturer: MuRata; Polarized: N; CompType: Capacitor; ValueDisplayed: 100pF; U/M: EA; Cap_F: 0.0000000001; Tolerance_%: 5; Value1: Unknown; VDC_V: 50; Value2: 50V; TaMin_C: -55; TaMax_C: 125; Cap_Case: 0603; SizeArea_mm2: 1.28; SizeAreaWB_mm2: 4.68; SizeX_mm: 1.6; SizeY_mm: 0.8; SizeZ_mm: 1; AEC Category: Q200
C25-C28 C48-C51 = C0603C103J3GECAUTO: CAP, CERM, 0.01 µF, 25 V,+/- 5%, C0G/NP0, AEC-Q200 Grade 1, 0603; Manufacturer: Kemet; Polarized: N; CompType: Capacitor; Value: 0.01uF; U/M: EA; Cap_F: 0.00000001; Tolerance_%: 5; VDC_V: 25; Value2: 25V; TaMin_C: -55; TaMax_C: 125; SizeArea_mm2: 1.28; SizeAreaWB_mm2: 4.68; SizeX_mm: 1.6; SizeY_mm: 0.8; SizeZ_mm: 1; AEC Category: Q200; AEC Qualified: Y
C29 C33 C34 C40 C44 C45 C47 C53 C136 C150 C166 C167 = CMP-0006752-5: CAP, CERM, 0.1 uF, 25 V, +/- 5%, X7R, 0603; PartNumber: 06033C104JAT2A; Manufacturer: AVX; Polarized: N; Value: 0.1uF; U/M: EA; Cap_F: 100nF; ESR_ohm: 0.05; Value1: 0.05 ohm; VDC_V: 25V; TaMin_C: -55°C; TaMax_C: 125°C; AEC Category: Q200; SizeArea_mm2: 1.28; SizeAreaWB_mm2: 4.68; SizeX_mm: 1.6; SizeY_mm: 0.8; SizeZ_mm: 1
C37 C38 = 885012205044: CAP, CERM, 1000 pF, 25 V,+/- 10%, X7R, 0402; Manufacturer: Wurth Elektronik; Polarized: N; CompType: Capacitor; Value: 1000pF; U/M: EA; Cap_F: 0.000000001; Tolerance_%: 10; VDC_V: 25; Value2: 25V; TaMin_C: -55; TaMax_C: 125; SizeArea_mm2: 0.5; SizeAreaWB_mm2: 3; SizeX_mm: 1; SizeZ_mm: 0.6; AEC Category: Q200
C41 = GRM155R71H122KA01D: CAP, CERM, 1200 pF, 50 V,+/- 10%, X7R, 0402; Manufacturer: MuRata; Polarized: N; CompType: Capacitor; Value: 1200pF; U/M: EA; Cap_F: 0.0000000012; Tolerance_%: 10; VDC_V: 50; Value2: 50V; TaMin_C: -55; TaMax_C: 125; SizeArea_mm2: 0.5; SizeAreaWB_mm2: 3; SizeX_mm: 1; SizeZ_mm: 0.6; AEC Category: Q200
C42 = GRM2195C1H752JA01D: CAP, CERM, 7500 pF, 50 V,+/- 5%, C0G/NP0, 0805; Manufacturer: MuRata; Polarized: N; CompType: Capacitor; Value: 7500pF; U/M: EA; Cap_F: 0.0000000075; Tolerance_%: 5; VDC_V: 50; Value2: 50V; TaMin_C: -55; TaMax_C: 125; Cap_Case: 0805; SizeArea_mm2: 2.5; SizeAreaWB_mm2: 6.75; SizeX_mm: 2; SizeY_mm: 1.25; SizeZ_mm: 1.45; AEC Category: Q200
C46 C55 = 06031C102JAT2A: CAP, CERM, 1000 pF, 100 V, +/- 5%, X7R, 0603; Manufacturer: AVX; Polarized: N; CompType: Capacitor; Value: 1000pF; U/M: EA; Cap_F: 0.000000001; Tolerance_%: 5; ESR_ohm: 0.276; Value1: 0.276 ohm; VDC_V: 100; Value2: 100V; TaMin_C: -55; TaMax_C: 125; SizeArea_mm2: 1.28; SizeAreaWB_mm2: 4.68; SizeX_mm: 1.6; SizeY_mm: 0.8; SizeZ_mm: 1; AEC Category: Q200
CS+1 CS-1 = CMP-0078143-2: TEST POINT.  No entry in BOM.
D1 D3 D4 = NSR0240V2T1G: Diode, Schottky, 40V, 0.25A, SOD-523; Manufacturer: ON Semiconductor; U/M: EA; Vf_V: 0.7; Value2: 0.7V; Io_A: 0.25; Vr_V: 40; TJmax_C: 150; RJC_CperW: 600
D2 = VS-20WT04FN: Diode FERD (Field Effect Rectifier Diode) 100V 20A Surface Mount DPAK; Manufacturer: STMicroelectronics; U/M: EA; Vf_V: 0.53; Value: 45V; Value2: 0.53V; Io_A: 20; Vr_V: 45; TJmax_C: 175; RJC_CperW: 1.2; Type: Schottky; SizeAreaWB_mm2: 101.7114; SizeArea_mm2: 64.8114; SizeX_mm: 9.91; SizeY_mm: 6.54; SizeZ_mm: 2.29; AEC Category: Q101; Green_Lifecycle: Not Set; Green_REACh: Incomplete
F1 = 6125FA15A: Fuse, 15 A, SMD; Manufacturer: Cooper Bussman; Irating_A: 15; Rtyp_Ohm: 0.004; MeltingTyp: 124
J1 J3 = CMP-0087889-1: Terminal Connector Rectangular Lug, Grounding 10-14 AWG 1/8 Stud; Manufacturer: Panduit; Symbol Name: SYM-CB25-18-CY; ContactFinish: Zinc; Voltage_V: 600V; Current_A: 25A
J2 = B2B-EH-A(LF)(SN): Header (Shrouded), 2.5mm, 2x1, Tin, TH; Manufacturer: JST Manufacturing; SymbolCreator: a0412235; Pitch_mm: 2.5; Gender: Male; Shrouded: Y; Row_Count: 1; Current_A: 3; Voltage_V: 250
L1 = CMP-0064071-1: Inductor, Shielded Drum Core, Powdered Iron, 1 uH, 5 A, 0.022 ohm, SMD; Manufacturer: Wurth Elektronik; Isat: 9A @ 20% inductance drop; Irms: 5A @ 40C rise; Green_Lifecycle: Active; SizeAreaWB_mm2: 27.577; DCR_ohm: 0.022; Green_REACh: Passed; Value: 1uH; Imax_A: 5A; SizeZ_mm: 2; SizeX_mm: 4.45; SizeY_mm: 4.06; SizeArea_mm2: 18.067; Ind_H: 1µH; AEC Category: Q200
L2 = CMP-0085394-1: Inductor, Shielded, Mn-Zn, 47 µH, 13 A, 0.00968 ohm, SMD; Manufacturer: Wurth Elektronik; SizeY_mm: 28; SizeZ_mm: 20.5; SizeAreaWB_mm2: 810; Value2: 13A; SizeArea_mm2: 700; Isat: 13A @ 30% inductance drop; AEC Qualified: N; DCR_ohm: 9.68m; AEC Category: Q200; Value: 47uH; SizeX_mm: 25; Irms: 18.7A @ 50C rise
Q1 Q7 = CMP-0000708-1: MOSFET, N-CH, 40 V, 15 A, DQJ0008A (VSONP-8); Alternate Manufacturer: None; Manufacturer: Texas Instruments; SizeZ_mm: 1.1; ChType: N; Value2: 7.7 nC; Value1: 0.009; VdsMax_V: 40V; SizeX_mm: 6; SizeY_mm: 4.9; Vgs_V: 20V; Value: 40V; Rdson45_ohm: 9.8m; SizeArea_mm2: 29.4; AEC Category: Q101; IdsMax_A: 15A; SizeAreaWB_mm2: 55.2; U/M: EA; QgTyp_nC: 7.7
R1 R5 R18 R24 R173 R174 = CMP-0022746-5: RES, 10.0 k, 1%, 0.1 W, 0603; Manufacturer: Yageo; Power_W: 100mW; TempCo: 100 ppm/C; Value_Code: 10k0; Value: 10.0k; EIA_Code: E96; Res_ohm: 10k; SizeX_mm: 1.6; SizeY_mm: 0.8; SizeZ_mm: 1; Value2: 0.1W; SizeArea_mm2: 1.28; AEC Qualified: N; VDC_V: 75V; AEC Category: Q200; SizeAreaWB_mm2: 4.68
R2 R3 R8 R172 R216 R217 R220 = RC0603JR-070RL: RES, 0, 5%, 0.1 W, 0603; Manufacturer: Yageo America; CompType: Resistor; Value: 0; Value_Code: 0000; Tolerance_%: 5; Power_W: 0.1; Value2: 0.1W; VDC_V: 50; TempCo: 200 ppm/C; SizeArea_mm2: 1.28; SizeX_mm: 1.6; SizeY_mm: 0.8; SizeZ_mm: 1; EIA_Code: E24; U/M: EA; AEC Category: Q200
R4 R9 = RC1206FR-0710RL: RES, 10.0, 1%, 0.25 W, 1206; Manufacturer: Yageo America; CompType: Resistor; Value: 10.0; Res_ohm: 10; Value_Code: 10R0; Tolerance_%: 1; Power_W: 0.25; Value2: 0.25W; VDC_V: 200; TempCo: 200 ppm/C; SizeArea_mm2: 5.12; SizeX_mm: 3.2; SizeY_mm: 1.6; SizeZ_mm: 1.35; EIA_Code: E96; U/M: EA; AEC Category: Q200
R6 R7 = Y14880R01000B9R: Current Sense Resistors - SMD 0.005ohms 0.1% 3w; Manufacturer: Vishay Foil Resistors; Value: 5mOhm; Value_Code: R010; Tolerance_%: 0.1; Power_W: 3; TempCo: 15 ppm/C; SizeArea_mm2: 85.935312; SizeAreaWB_mm2: 127.019312; SizeX_mm: 9.398; SizeY_mm: 9.144; SizeZ_mm: 0.889; U/M: EA; AEC Category: Q200; AEC Qualified: N
R10 R12-R17 R20 R28 R29 R31 R32 R41 R43 R45 R47-R49 R159-R161 R175 R185 R186 R192 R193 R219 = CRCW04020000Z0ED: RES, 0, 5%, 0.063 W, 0402; Manufacturer: Vishay-Dale; CompType: Resistor; Value: 0; Value_Code: 0000; Tolerance_%: 5; Power_W: 0.063; Value2: 0.063W; VDC_V: 50; TempCo: 200 ppm/C; SizeArea_mm2: 0.5; SizeX_mm: 1; SizeZ_mm: 0.6; EIA_Code: E24; U/M: EA; AEC Category: Q200; Green_Lifecycle: Active; Green_REACh: Passed
R11 R21 = CRCW06032R00FKEA: RES, 2.00, 1%, 0.1 W, 0603; Manufacturer: Vishay-Dale; CompType: Resistor; Value: 2.00; Res_ohm: 2; Value_Code: 2R00; Tolerance_%: 1; Power_W: 0.1; Value2: 0.1W; VDC_V: 75; TempCo: 100 ppm/C; SizeArea_mm2: 1.28; SizeX_mm: 1.6; SizeY_mm: 0.8; EIA_Code: E96; U/M: EA; AEC Category: Q200; Green_Lifecycle: Active; Green_REACh: Passed
R19 R25 = CMP-0022900-4: RES, 1.00, 1%, 0.1 W, 0603; Manufacturer: Yageo; Power_W: 100mW; TempCo: 200 ppm/C; Value_Code: 1R00; Value: 1.00; EIA_Code: E96; SizeX_mm: 1.6; SizeY_mm: 0.8; Value2: 0.1W; SizeArea_mm2: 1.28; AEC Qualified: N; VDC_V: 75V; AEC Category: Q200; SizeAreaWB_mm2: 4.68
R22 R23 R26 R27 R61 R62 R76 R79 R162 R204 R218 = CRCW040210K0FKED: RES, 10.0 k, 1%, 0.063 W, 0402; Manufacturer: Vishay-Dale; CompType: Resistor; Value: 10.0k; Res_ohm: 10000; Value_Code: 10k0; Tolerance_%: 1; Power_W: 0.063; Value2: 0.063W; VDC_V: 50; TempCo: 100 ppm/C; SizeArea_mm2: 0.5; SizeZ_mm: 0.6; EIA_Code: E96; U/M: EA; AEC Category: Q200; Green_Lifecycle: Active; Green_REACh: Passed
R30 = CMP-0024060-1: RES, 2.15 k, 0.1%, 0.1 W, 0603; Manufacturer: Yageo America; Power_W: 100mW; TempCo: 25 ppm/C; Value_Code: 2k15; U/M: EA; Value: 2.15k; EIA_Code: E192; SizeX_mm: 1.6; SizeY_mm: 0.8; SizeZ_mm: 1; Value2: 0.1W; SizeArea_mm2: 1.28; VDC_V: 75V; AEC Category: Q200
R33-R40 R65-R68 R71-R74 = PNM0402E5000BST1: RES, 500, 0.1%, 0.05 W, 0402; Manufacturer: Vishay Thin Film; CompType: Resistor; Value: 500; Value_Code: 500R; Tolerance_%: 0.1; Power_W: 0.05; Value2: 0.05W; VDC_V: 75; TempCo: 25 ppm/C; SizeArea_mm2: 0.5; SizeX_mm: 1; SizeZ_mm: 0.6; U/M: EA; AEC Category: Q200; AEC Qualified: N
R44 = RT0603BRD072KL: RES, 2.00 k, 0.1%, 0.1 W, 0603; Manufacturer: Yageo America; CompType: Resistor; Value: 2.00k; Res_ohm: 2000; Value_Code: 2k00; Tolerance_%: 0.1; Value2: 0.1W; VDC_V: 75; TempCo: 25 ppm/C; SizeArea_mm2: 1.28; SizeX_mm: 1.6; SizeY_mm: 0.8; SizeZ_mm: 1; EIA_Code: E192; U/M: EA; AEC Category: Q200
R46 = RT0603BRD077K96L: RES, 7.96 k, 0.1%, 0.1 W, 0603; Manufacturer: Yageo America; CompType: Resistor; Value: 7.96k; Res_ohm: 7960; Value_Code: 7k96; Tolerance_%: 0.1; Value2: 0.1W; VDC_V: 75; TempCo: 25 ppm/C; SizeArea_mm2: 1.28; SizeX_mm: 1.6; SizeY_mm: 0.8; SizeZ_mm: 1; EIA_Code: E192; U/M: EA; AEC Category: Q200
R50 = CRCW04022K70JNED: RES, 2.7 k, 5%, 0.063 W, 0402; Manufacturer: Vishay-Dale; CompType: Resistor; Value: 2.7k; Res_ohm: 2700; Value_Code: 2k70; Tolerance_%: 5; Power_W: 0.063; Value2: 0.063W; VDC_V: 50; TempCo: 200 ppm/C; SizeArea_mm2: 0.5; SizeX_mm: 1; SizeZ_mm: 0.6; EIA_Code: E24; U/M: EA; AEC Category: Q200; Green_Lifecycle: Active; Green_REACh: Passed
R51 = CRCW04025K10JNED: RES, 5.1 k, 5%, 0.063 W, 0402; Manufacturer: Vishay-Dale; CompType: Resistor; Value: 5.1k; Res_ohm: 5100; Value_Code: 5k10; Tolerance_%: 5; Power_W: 0.063; Value2: 0.063W; VDC_V: 50; TempCo: 200 ppm/C; SizeArea_mm2: 0.5; SizeX_mm: 1; SizeZ_mm: 0.6; EIA_Code: E24; U/M: EA; AEC Category: Q200; Green_Lifecycle: Active; Green_REACh: Passed
R52 = CRCW04027K50FKED: RES, 7.50 k, 1%, 0.063 W, 0402; Manufacturer: Vishay-Dale; CompType: Resistor; Value: 7.50k; Res_ohm: 7500; Value_Code: 7k50; Tolerance_%: 1; Power_W: 0.063; Value2: 0.063W; VDC_V: 50; TempCo: 100 ppm/C; SizeArea_mm2: 0.5; SizeZ_mm: 0.6; EIA_Code: E96; U/M: EA; AEC Category: Q200; Green_Lifecycle: Active; Green_REACh: Passed
R53 = CRCW040211K0FKED: RES, 11.0 k, 1%, 0.063 W, 0402; Manufacturer: Vishay-Dale; CompType: Resistor; Value: 11.0k; Res_ohm: 11000; Value_Code: 11k0; Tolerance_%: 1; Power_W: 0.063; Value2: 0.063W; VDC_V: 50; TempCo: 100 ppm/C; SizeArea_mm2: 0.5; SizeZ_mm: 0.6; EIA_Code: E96; U/M: EA; AEC Category: Q200
R63 R77 = CMP-0023991-3: RES, 24.0 k, 0.1%, 0.1 W, 0603; Manufacturer: Yageo America; Power_W: 100mW; TempCo: 25 ppm/C; Value_Code: 24k0; U/M: EA; Value: 24.0k; Res_ohm: 24k; SizeX_mm: 1.6; SizeY_mm: 0.8; SizeZ_mm: 1; Value2: 0.1W; SizeArea_mm2: 1.28; VDC_V: 75V; AEC Category: Q200; EIA_Code: E192
R64 R70 = CMP-0023630-3: RES, 100 k, 0.1%, 0.1 W, 0603; Manufacturer: Yageo America; Power_W: 100mW; TempCo: 25 ppm/C; U/M: EA; Value: 100k; EIA_Code: E192; SizeX_mm: 1.6; SizeY_mm: 0.8; SizeZ_mm: 1; Value2: 0.1W; SizeArea_mm2: 1.28; VDC_V: 75V; AEC Category: Q200
R69 = CRCW06033K32FKEA: RES, 3.32 k, 1%, 0.1 W, 0603; Manufacturer: Vishay-Dale; CompType: Resistor; Value: 3.32k; Res_ohm: 3320; Value_Code: 3k32; Tolerance_%: 1; Power_W: 0.1; Value2: 0.1W; VDC_V: 75; TempCo: 100 ppm/C; EIA_Code: E96; U/M: EA
R75 R78 = CRCW060310K0FKEA: RES, 10.0 k, 1%, 0.1 W, 0603; Manufacturer: Vishay-Dale; CompType: Resistor; Value: 10.0k; Res_ohm: 10000; Value_Code: 10k0; Tolerance_%: 1; Power_W: 0.1; Value2: 0.1W; VDC_V: 75; TempCo: 100 ppm/C; EIA_Code: E96; U/M: EA
TP1 TP3 TP7-TP10 = 5002: Test Point, Miniature, White, TH; Manufacturer: Keystone; CompType: Test Point Loop; ContactFinish: Silver; Green_Lifecycle: Active; Green_REACh: Passed
TP2 TP4 TP5 = 5000: Test Point, Miniature, Red, TH; Manufacturer: Keystone; CompType: Test Point Loop; ContactFinish: Silver; Green_Lifecycle: Active; Green_REACh: Passed
TP6 = 5001: Test Point, Miniature, Black, TH; Manufacturer: Keystone; CompType: Test Point Loop; ContactFinish: Silver; Green_Lifecycle: Active; Green_REACh: Passed
U1 = CMP-0071433-1: High Voltage 1A Peak Half Bridge Gate Driver, 8-pin Narrow SOIC, Pb-Free; Manufacturer: Texas Instruments; PowerWise: N; CompType: MiscPower; PackageTopMarking: NSZXTT*L5109*BMA
U2 U24 = CMP-0051216-2: Single 3-Input Positive-AND Gate, DCK0006A, LARGE T&R; Manufacturer: Texas Instruments; Output Type: CMOS; Bits(#): 1; Input Type: CMOS/TTL; Technology Family: LVC; Schmitt Trigger: No; VCC(Max)(V): 5.5; Gate Type: AND; Rating: Catalog; Output Drive (IOL/IOH)(Max)(mA): 32/-32; ICC @ Nom Voltage(Max)(mA): 0.01; VCC(Min)(V): 1.65; F @ Nom Voltage(Max)(Mhz): 150; Logic: True; Voltage(Nom)(V): 1.8,2.5,3.3,5; tpd @ Nom Voltage(Max)(ns): 20,7.8,6.2,4.6
U3 = CMP-0860958-1: 4.7MHz, 35µV offset, 7nV/√Hz noise, low-power, super beta precision instrumentation amplifier, D0008A (SOIC-8); Manufacturer: Texas Instruments; SizeX_mm: 4.9; AEC Qualified: N; Rating: Catalog; CompType: IC; SizeArea_mm2: 30.38; AEC Category: Q200; SizeY_mm: 6.2; SizeAreaWB_mm2: 56.58; SizeZ_mm: 1.75
U4 = CMP-0065137-4: Low Supply, Voltage Output, Low- or High-Side Measurement, Bidirectional, Zero-Drift Series, Current-Shunt Monitor, DCK0006A (SOT-SC70-6); Manufacturer: Texas Instruments; SizeZ_mm: 1.1; SizeX_mm: 2.1; SizeY_mm: 2.0; SizeArea_mm2: 4.2; CompType: IC; SizeAreaWB_mm2: 9.3; AEC Category: Q200; AEC Qualified: N
U5 U10 U32 = CMP-0073526-1: 36V, Low-Power, RRO, General-Purpose Operational Amplifier, DBV0005A (SOT-23-5); Alternate PartNumber: TLV171IDBVT; Alternate Manufacturer: Texas Instruments; SizeAreaWB_mm2: 14.82; U/M: EA; SizeZ_mm: 1.45; SizeX_mm: 2.8; SizeY_mm: 2.9; SizeArea_mm2: 8.12; CompType: IC
U6 = CMP-0073529-1: 36V, Low Power, RRO, General Purpose Operational Amplifier, D0008A (SOIC-8); Alternate Manufacturer: Texas Instruments; SizeAreaWB_mm2: 56.58; U/M: EA; SizeZ_mm: 1.75; SizeX_mm: 4.9; SizeY_mm: 6.2; SizeArea_mm2: 30.38; CompType: IC
U9 = LM393AD: Dual Comparator, D0008A; Manufacturer: Texas Instruments; CompType: OpAmp IC
U29 = CMP-0076523-1: CMOS Triple 2-Channel Analog Multiplexer/Demultiplexer with Logic-Level Conversion, PW0016A (TSSOP-16); Manufacturer: Texas Instruments; SizeAreaWB_mm2: 58.8; SizeArea_mm2: 32.0; SizeZ_mm: 1.2; SizeY_mm: 5.0; U/M: EA; CompType: IC; SizeX_mm: 6.4
U30 = CMP-0073515-1: 2.2-V to 36-V, microPower Comparator, DBV0005A (SOT-23-5); Alternate PartNumber: TLV1701AIDBVT; Alternate Manufacturer: Texas Instruments; SizeAreaWB_mm2: 14.82; U/M: EA; SizeZ_mm: 1.45; SizeX_mm: 2.8; SizeY_mm: 2.9; SizeArea_mm2: 8.12; CompType: IC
